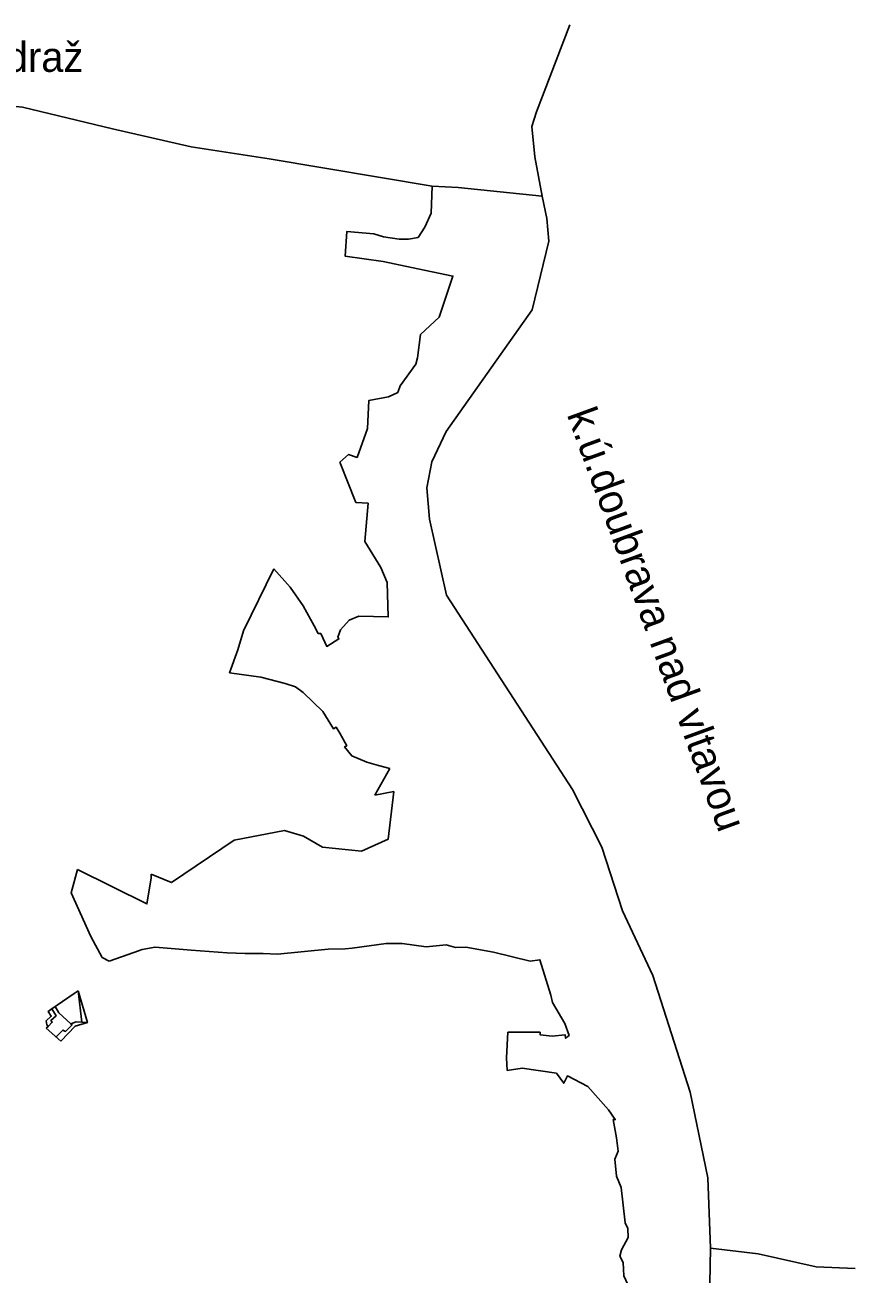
# Model space of a CAD drawing. Extents: x -764981 to -759318, y -1137368 to -1131930.
# Drawn here: x -762113 to -760863, y -1133883 to -1132003 of the extents above; entities that cross this region are included whole.
import ezdxf

# ---------------------------------------------------------------- set-up
doc = ezdxf.new("R2010")
doc.units = 0
for name, color, linetype in [('Vrstva 41', 7, 'Continuous'), ('Vrstva 42', 7, 'Continuous'), ('Vrstva 43', 7, 'Continuous'), ('Vrstva 44', 7, 'Continuous'), ('Vrstva 45', 7, 'Continuous')]:
    doc.layers.add(name, color=color, linetype=linetype)

msp = doc.modelspace()

# ---------------------------------------------------------------- linework, layer by layer
at = {"layer": 'Vrstva 41'}
for p, q in [((-761745.1, -1132204.4), (-761499.8, -1132245.4)), ((-761738.1, -1132821.6), (-761783.9, -1132914.8)), ((-761783.9, -1132914.8), (-761792.2, -1132943.3)), ((-761563.2, -1133122.1), (-761586, -1133162.5)), ((-761586, -1133162.5), (-761557.4, -1133156.8))]:
    msp.add_line(p, q, dxfattribs=at)
for points in [[(-762328.6, -1132111.8), (-762267.8, -1132111.8), (-762116.8, -1132126.6), (-761980.9, -1132159.3)], [(-761980.9, -1132159.3), (-761862.5, -1132186.5), (-761745.1, -1132204.4)], [(-761499.8, -1132245.4), (-761501.4, -1132286.2), (-761510.5, -1132307.4), (-761520.9, -1132322.9), (-761535.3, -1132325.1), (-761549.5, -1132325.3)], [(-761549.5, -1132325.3), (-761573, -1132321.6), (-761587.5, -1132317.2), (-761628.4, -1132314), (-761630.5, -1132351), (-761573.5, -1132358.8), (-761530.9, -1132367.8)], [(-761530.9, -1132367.8), (-761468.4, -1132381), (-761489.4, -1132442.7), (-761517.5, -1132468.9), (-761521.9, -1132504.2)], [(-761521.9, -1132504.2), (-761524.4, -1132513.4), (-761547.9, -1132546.1), (-761551.5, -1132556.1), (-761565.7, -1132562.6), (-761595.2, -1132568.4), (-761597, -1132610.4), (-761612.7, -1132653.9), (-761625.5, -1132649.3), (-761638.8, -1132661)], [(-761638.8, -1132661), (-761614.5, -1132721.5), (-761596.1, -1132722.7)], [(-761596.1, -1132722.7), (-761601.2, -1132780.5), (-761577.1, -1132819.5), (-761567.3, -1132842)], [(-761667.1, -1132918.9), (-761671.4, -1132918.8), (-761677.6, -1132907.5), (-761693.8, -1132877.5), (-761713.5, -1132849), (-761738.1, -1132821.6)], [(-761567.3, -1132842), (-761565.8, -1132894), (-761610.1, -1132892.7), (-761624.7, -1132899.1), (-761637.5, -1132913.6), (-761641.7, -1132924.5), (-761640.1, -1132927.2), (-761658.4, -1132938.3), (-761667.1, -1132918.9)], [(-761792.2, -1132943.3), (-761804.7, -1132978.1), (-761757.5, -1132984.7), (-761720.9, -1132994)], [(-761720.9, -1132994), (-761705.7, -1132999.2), (-761694, -1133007.9), (-761664.3, -1133036.5), (-761648.3, -1133062.2), (-761644.5, -1133059.8), (-761638.7, -1133069.1)], [(-761638.7, -1133069.1), (-761628.3, -1133087.8), (-761631.6, -1133089.6), (-761620.9, -1133103.3), (-761597.9, -1133112.8)], [(-761597.9, -1133112.8), (-761580.6, -1133117.4), (-761563.2, -1133122.1)], [(-761557.4, -1133156.8), (-761565.8, -1133228.3), (-761606, -1133246.5)], [(-761606, -1133246.5), (-761664.8, -1133240.6), (-761693.7, -1133224.2), (-761722.2, -1133215.6), (-761797.7, -1133230.1), (-761892.2, -1133293.8), (-761922.7, -1133281.3)], [(-762033.9, -1133274.1), (-762043.1, -1133309.3), (-762013.6, -1133375.2), (-761996.4, -1133406.5), (-761986.3, -1133412.2)], [(-761922.7, -1133281.3), (-761922.7, -1133287.1), (-761929.2, -1133326.1), (-762033.9, -1133274.1)], [(-761986.3, -1133412.2), (-761949.1, -1133398.9), (-761936.6, -1133394.4), (-761917, -1133391), (-761862.8, -1133395.4)], [(-761754, -1133400.6), (-761732.7, -1133401.7), (-761656.1, -1133394.1), (-761630.5, -1133393.7), (-761620.3, -1133392.4), (-761569, -1133385.7)], [(-761569, -1133385.7), (-761544.8, -1133385.7), (-761508.7, -1133390.6), (-761478.8, -1133387.8), (-761464.5, -1133391.5)], [(-761464.5, -1133391.5), (-761449.1, -1133391.2), (-761407.3, -1133398.8), (-761352, -1133412.2), (-761337.4, -1133410.1), (-761321.1, -1133463.2)], [(-761862.8, -1133395.4), (-761808.4, -1133399.4), (-761781.5, -1133400.6), (-761754, -1133400.6)], [(-761321.1, -1133463.2), (-761318.7, -1133474.4), (-761299.7, -1133505.8), (-761293.6, -1133524.2), (-761298.9, -1133528.1), (-761299.3, -1133523.2), (-761319.1, -1133525), (-761337.1, -1133523), (-761337.1, -1133519.3), (-761385.9, -1133519.3)], [(-761385.9, -1133519.3), (-761387.6, -1133557.6), (-761386.5, -1133576.8)], [(-761386.5, -1133576.8), (-761364.3, -1133573.3), (-761312.7, -1133580.6)], [(-761312.7, -1133580.6), (-761301.6, -1133596), (-761296, -1133584.9), (-761265.1, -1133600.7), (-761234.1, -1133635.9), (-761224, -1133650.6), (-761227.3, -1133650.6)], [(-761227.3, -1133650.6), (-761221.9, -1133678.3), (-761219.8, -1133698.4)], [(-761219.8, -1133698.4), (-761224.4, -1133710.4), (-761222.2, -1133735.9), (-761215.3, -1133753)], [(-761215.3, -1133753), (-761209, -1133806.1), (-761205.1, -1133814.4), (-761204.7, -1133827.9), (-761214.7, -1133846.5)], [(-761214.7, -1133846.5), (-761217.2, -1133856), (-761212.1, -1133865.8), (-761211.2, -1133885.6), (-761196.3, -1133917.4), (-761184.3, -1133963.9)]]:
    msp.add_lwpolyline(points, dxfattribs=at)
at = {"layer": 'Vrstva 42'}
msp.add_line((-762080.8, -1133512.9), (-762059, -1133532.8), dxfattribs=at)
for points in [[(-762033, -1133456.7), (-762038.8, -1133460.9), (-762074, -1133485.1), (-762078.2, -1133488), (-762073.4, -1133495), (-762080.8, -1133501.9), (-762079.8, -1133507.9), (-762077.8, -1133510.3), (-762080.8, -1133512.9)], [(-762033, -1133456.7), (-762018.9, -1133504.7), (-762037.4, -1133510.2), (-762059, -1133532.8)]]:
    msp.add_lwpolyline(points, dxfattribs=at)
at = {"layer": 'Vrstva 43'}
msp.add_line((-762033, -1133456.7), (-762027.3, -1133504.1), dxfattribs=at)
for points in [[(-762072.4, -1133484.1), (-762066, -1133494.4), (-762073.9, -1133501.6), (-762071.7, -1133504), (-762077.8, -1133510.3)], [(-762044, -1133506.6), (-762061.7, -1133489.8), (-762067.6, -1133480.3)], [(-762018.9, -1133504.7), (-762027.3, -1133504.1), (-762035.8, -1133503.4), (-762044, -1133506.6), (-762041.9, -1133508), (-762052, -1133518), (-762055.7, -1133516), (-762066.2, -1133526.8)]]:
    msp.add_lwpolyline(points, dxfattribs=at)
at = {"layer": 'Vrstva 44'}
for q in [(-761499.8, -1132245.4), (-761334, -1132260.6)]:
    msp.add_line((-761460.4, -1132247.7), q, dxfattribs=at)
for points in [[(-761507.8, -1132699.8), (-761500.2, -1132660.4), (-761478.6, -1132614.8), (-761349.1, -1132431.9), (-761323.8, -1132328.6), (-761327.1, -1132294.2), (-761334, -1132260.6)], [(-761503.7, -1132746.8), (-761507.8, -1132699.8)], [(-761244, -1133240.5), (-761288.2, -1133153.9), (-761478, -1132861.2), (-761503.7, -1132746.8)], [(-761084.5, -1133738.3), (-761111, -1133609.4), (-761167.2, -1133433.5), (-761212.9, -1133336.6), (-761244, -1133240.5)], [(-761045, -1134299.3), (-761084.5, -1134057.3), (-761080.8, -1133844), (-761084.5, -1133738.3)]]:
    msp.add_lwpolyline(points, dxfattribs=at)
at = {"layer": 'Vrstva 45'}
for points in [[(-761334, -1132260.6), (-761345.3, -1132201.5), (-761349.6, -1132155.6), (-761342.6, -1132133.8), (-761292.5, -1132002.9)], [(-761080.8, -1133844), (-761008.9, -1133852.7), (-760921.6, -1133872.2), (-760862.9, -1133874.7)]]:
    msp.add_lwpolyline(points, dxfattribs=at)

# ---------------------------------------------------------------- texts
msp.add_text('k.ú.údraž', height=45, dxfattribs=at).set_placement((-762272.3, -1132073.5))
msp.add_text('k.ú.doubrava nad vltavou', height=45, rotation=290, dxfattribs=at).set_placement((-761297.3, -1132588.9))

doc.saveas('drawing.dxf')
